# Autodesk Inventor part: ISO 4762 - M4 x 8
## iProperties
Comments: To add or edit properties for Autodesk Inventor files, use iProperties.
Created: 2004-08
Part Number: ISO 4762 - M4 x 8
Vendor: Autodesk Inc.
Document SubType Name: Modeling
Designer: John Blackburn
Material: Default
Description: Hexagon Socket Head Cap Screw
Standard: ISO 4762
Size Designation: M4 x 8
Alert: To add or edit properties for Autodesk Inventor files, use iProperties.
Control State: 0
Master: False
Checked Out: False
Shininess: 64.0
Length Units: 11269
Angle Units: 11279
Time Units: 11290
Mass Units: 11283
Length Display Precision: 3
Angle Display Precision: 2
Compacted: True
EGR: 1
Density: 0.0
Volumn: 0.0
Area: 0.0
PropertySet Name: Model Information
Author: John Blackburn
Revision Number: 8
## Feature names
1. Body [Revolution]
2. Slot [Extrusion]
3. Fillet1
4. Chamfer1
